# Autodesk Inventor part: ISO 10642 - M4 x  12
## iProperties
Comments: To add or edit properties for Autodesk Inventor files, use iProperties.
Created: 2004-08
Part Number: ISO 10642 - M4 x  12
Vendor: Autodesk Inc.
Document SubType Name: Modeling
Designer: John Blackburn
Material: Default
Description: Hexagon Socket Countersunk Head Screw
Standard: ISO 10642
Alert: To add or edit properties for Autodesk Inventor files, use iProperties.
Control State: 0
Master: False
Checked Out: False
Shininess: 64.0
Length Units: 11269
Angle Units: 11279
Time Units: 11290
Mass Units: 11283
Length Display Precision: 3
Angle Display Precision: 2
Compacted: True
EGR: 1
Density: 0.0
Volumn: 0.0
Area: 0.0
PropertySet Name: Model Information
Author: John Blackburn
Revision Number: 8
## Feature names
1. Body [Revolution]
2. Slot [Extrusion]
3. Chamfer1
